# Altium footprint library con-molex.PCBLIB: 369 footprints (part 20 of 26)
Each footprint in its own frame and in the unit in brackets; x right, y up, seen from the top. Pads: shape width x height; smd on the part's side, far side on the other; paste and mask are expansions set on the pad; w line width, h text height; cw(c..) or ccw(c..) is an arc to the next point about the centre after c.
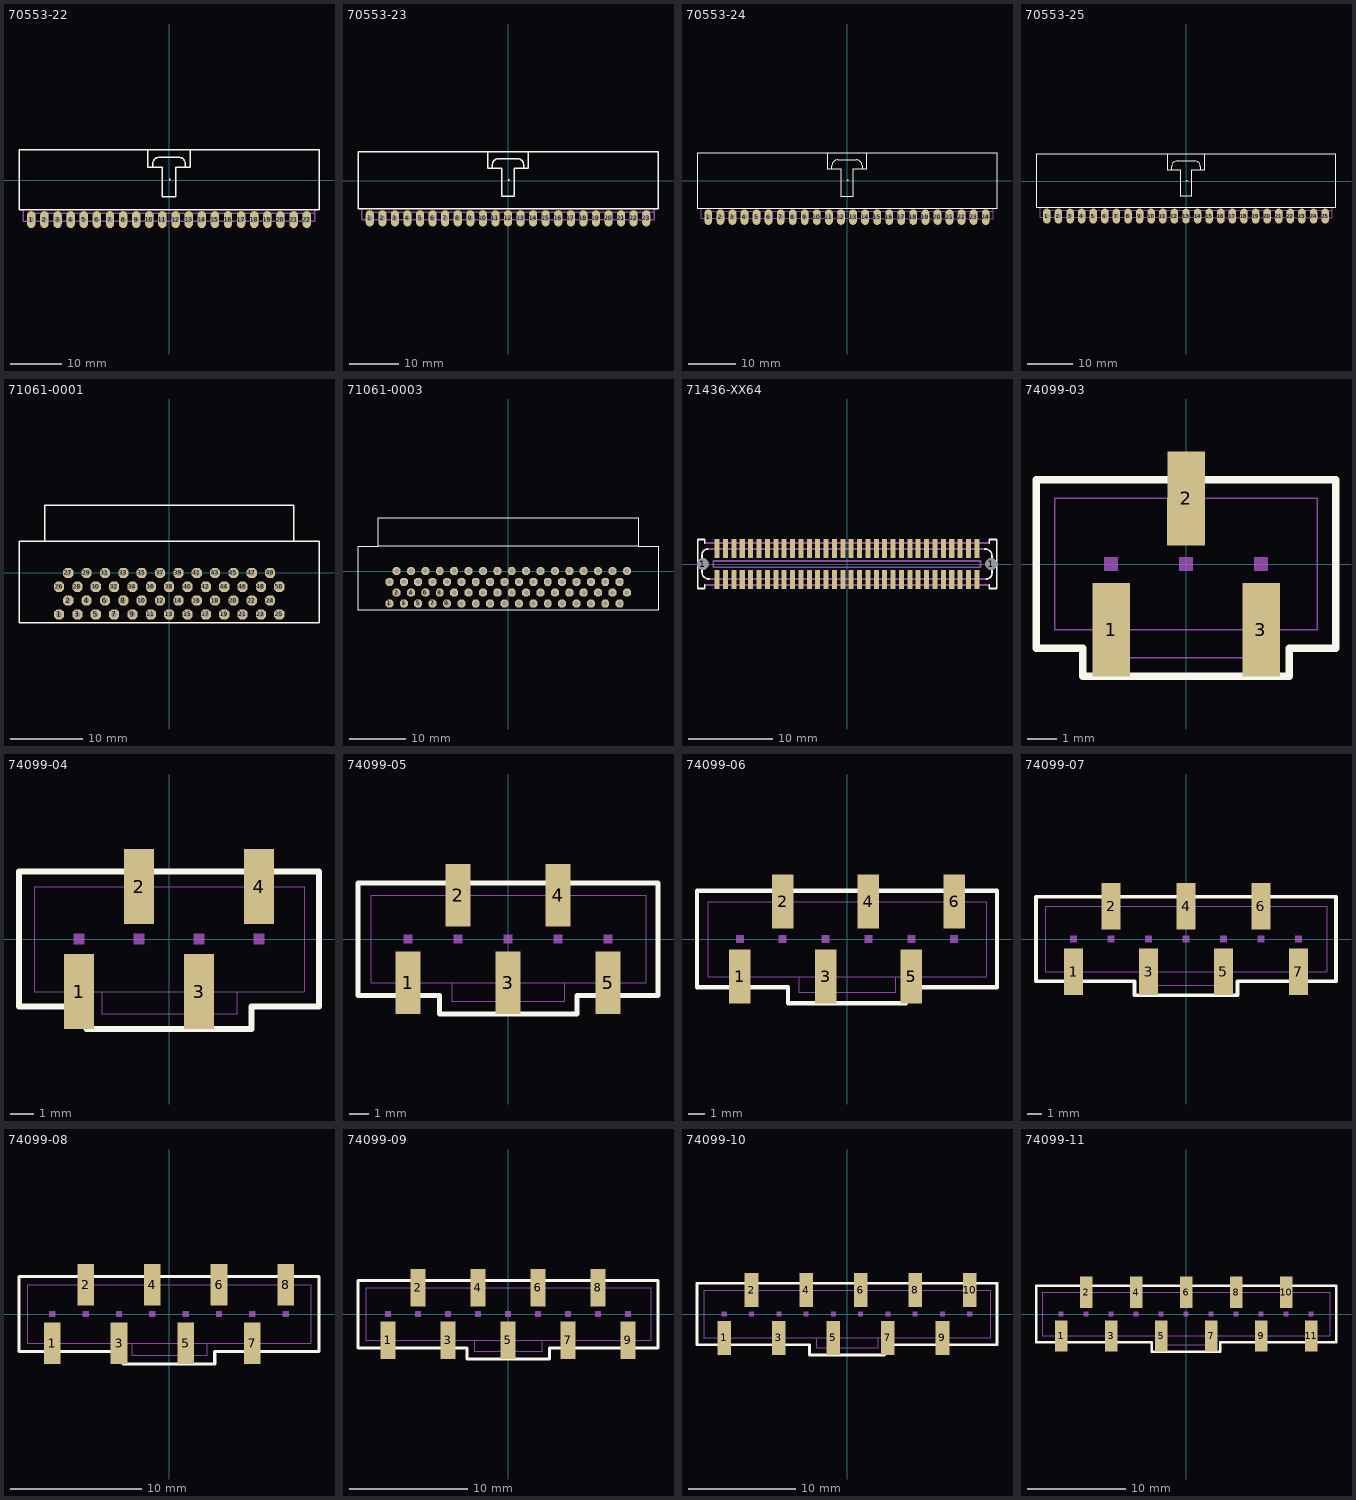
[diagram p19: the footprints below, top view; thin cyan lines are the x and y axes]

## 70553-22 [mil]
pads (22):
  oval 64.5x129 hole 43: 1(-1050,-300) 2(-950,-300) 3(-850,-300) 4(-750,-300) 5(-650,-300) 6(-550,-300) 7(-450,-300) 8(-350,-300) 9(-250,-300) 10(-150,-300) 11(-50,-300) 12(50,-300) 13(150,-300) 14(250,-300) 15(350,-300) 16(450,-300) 17(550,-300) 18(650,-300) 19(750,-300) 20(850,-300) 21(950,-300) 22(1050,-300)
Top Overlay:
  region: 0,0 10,0 10,10 0,10
  lines w10: -162.5,231.25 -162.5,100 -125,100 ; -125,100 -50,100 -50,-125 50,-125 50,100 125,100 ; -125,100 -125,125 cw(c-75,125) -75,175 75,175 cw(c75,125) 125,125 125,100 ; 125,100 162.5,100 162.5,231.25 ; 162.5,231.25 1143.75,231.25 1143.75,-225 -1143.75,-225 -1143.75,231.25 162.5,231.25
Mechanical 16:
  drawing of 178 lines, arcs and shapes, not listed

## 70553-23 [mil]
pads (23):
  oval 64.5x129 hole 43: 1(-1100,-300) 2(-1000,-300) 3(-900,-300) 4(-800,-300) 5(-700,-300) 6(-600,-300) 7(-500,-300) 8(-400,-300) 9(-300,-300) 10(-200,-300) 11(-100,-300) 12(0,-300) 13(100,-300) 14(200,-300) 15(300,-300) 16(400,-300) 17(500,-300) 18(600,-300) 19(700,-300) 20(800,-300) 21(900,-300) 22(1000,-300) 23(1100,-300)
Top Overlay:
  region: 0,0 10,0 10,10 0,10
  lines w10: -162.5,231.25 -162.5,100 -125,100 ; -125,100 -50,100 -50,-125 50,-125 50,100 125,100 ; -125,100 -125,125 cw(c-75,125) -75,175 75,175 cw(c75,125) 125,125 125,100 ; 125,100 162.5,100 162.5,231.25 ; 162.5,231.25 1193.75,231.25 1193.75,-225 -1193.75,-225 -1193.75,231.25 162.5,231.25
Mechanical 16:
  drawing of 186 lines, arcs and shapes, not listed

## 70553-24 [mil]
pads (24):
  oval 64.5x129 hole 43: 1(-1150,-300) 2(-1050,-300) 3(-950,-300) 4(-850,-300) 5(-750,-300) 6(-650,-300) 7(-550,-300) 8(-450,-300) 9(-350,-300) 10(-250,-300) 11(-150,-300) 12(-50,-300) 13(50,-300) 14(150,-300) 15(250,-300) 16(350,-300) 17(450,-300) 18(550,-300) 19(650,-300) 20(750,-300) 21(850,-300) 22(950,-300) 23(1050,-300) 24(1150,-300)
Top Overlay:
  region: 0,0 10,0 10,10 0,10
  lines w10: -162.5,231.25 -162.5,100 -125,100 ; -125,100 -50,100 -50,-125 50,-125 50,100 125,100 ; -125,100 -125,125 cw(c-75,125) -75,175 75,175 cw(c75,125) 125,125 125,100 ; 125,100 162.5,100 162.5,231.25 ; 162.5,231.25 1243.75,231.25 1243.75,-225 -1243.75,-225 -1243.75,231.25 162.5,231.25
Mechanical 16:
  drawing of 194 lines, arcs and shapes, not listed

## 70553-25 [mil]
pads (25):
  oval 64.5x129 hole 43: 1(-1200,-300) 2(-1100,-300) 3(-1000,-300) 4(-900,-300) 5(-800,-300) 6(-700,-300) 7(-600,-300) 8(-500,-300) 9(-400,-300) 10(-300,-300) 11(-200,-300) 12(-100,-300) 13(0,-300) 14(100,-300) 15(200,-300) 16(300,-300) 17(400,-300) 18(500,-300) 19(600,-300) 20(700,-300) 21(800,-300) 22(900,-300) 23(1000,-300) 24(1100,-300) 25(1200,-300)
Top Overlay:
  region: 0,0 10,0 10,10 0,10
  lines w10: -162.5,231.25 -162.5,100 -125,100 ; -125,100 -50,100 -50,-125 50,-125 50,100 125,100 ; -125,100 -125,125 cw(c-75,125) -75,175 75,175 cw(c75,125) 125,125 125,100 ; 125,100 162.5,100 162.5,231.25 ; 162.5,231.25 1293.75,231.25 1293.75,-225 -1293.75,-225 -1293.75,231.25 162.5,231.25
Mechanical 16:
  drawing of 202 lines, arcs and shapes, not listed

## 71061-0001 [mil]
pads (50):
  oct 55x55 hole 32: 1(-600,-225.59) 2(-550,-150.39) 3(-500,-225.59) 4(-450,-150.39) 5(-400,-225.59) 6(-350,-150.39) 7(-300,-225.59) 8(-250,-150.39) 9(-200,-225.59) 10(-150,-150.39) 11(-100,-225.59) 12(-50,-150.39) 13(0,-225.59) 14(50,-150.39) 15(100,-225.59) 16(150,-150.39) 17(200,-225.59) 18(250,-150.39) 19(300,-225.59) 20(350,-150.39) 21(400,-225.59) 22(450,-150.39) 23(500,-225.59) 24(550,-150.39) 25(600,-225.59) 26(-600,-75.2) 27(-550,0) 28(-500,-75.2) 29(-450,0) 30(-400,-75.2) 31(-350,0) 32(-300,-75.2) 33(-250,0) 34(-200,-75.2) 35(-150,0) 36(-100,-75.2) 37(-50,0) 38(0,-75.2) 39(50,0) 40(100,-75.2) 41(150,0) 42(200,-75.2) 43(250,0) 44(300,-75.2) 45(350,0) 46(400,-75.2) 47(450,0) 48(500,-75.2) 49(550,0) 50(600,-75.2)
Top Overlay:
  lines w8: -678.54,171.85 -818.31,171.85 -818.31,-271.06 816.34,-271.06 816.34,171.85 678.54,171.85 ; -678.54,171.85 -678.54,368.7 678.54,368.7 678.54,171.85 ; -678.54,171.85 678.54,171.85

## 71061-0003 [mil]
pads (68):
  oct 55x55 hole 32: 1(-825,-225.59) 2(-775,-150.39) 3(-725,-225.59) 4(-675,-150.39) 5(-625,-225.59) 6(-575,-150.39) 7(-525,-225.59) 8(-475,-150.39) 9(-425,-225.59) 10(-375,-150.39) 11(-325,-225.59) 12(-275,-150.39) 13(-225,-225.59) 14(-175,-150.39) 15(-125,-225.59) 16(-75,-150.39) 17(-25,-225.59) 18(25,-150.39) 19(75,-225.59) 20(125,-150.39) 21(175,-225.59) 22(225,-150.39) 23(275,-225.59) 24(325,-150.39) 25(375,-225.59) 26(425,-150.39) 27(475,-225.59) 28(525,-150.39) 29(575,-225.59) 30(625,-150.39) 31(675,-225.59) 32(725,-150.39) 33(775,-225.59) 34(825,-150.39) 35(-825,-75.2) 36(-775,0) 37(-725,-75.2) 38(-675,0) 39(-625,-75.2) 40(-575,0) 41(-525,-75.2) 42(-475,0) 43(-425,-75.2) 44(-375,0) 45(-325,-75.2) 46(-275,0) 47(-225,-75.2) 48(-175,0) 49(-125,-75.2) 50(-75,0) 51(-25,-75.2) 52(25,0) 53(75,-75.2) 54(125,0) 55(175,-75.2) 56(225,0) 57(275,-75.2) 58(325,0) 59(375,-75.2) 60(425,0) 61(475,-75.2) 62(525,0) 63(575,-75.2) 64(625,0) 65(675,-75.2) 66(725,0) 67(775,-75.2) 68(825,0)
Top Overlay:
  lines w8: -903.54,171.85 -1043.31,171.85 -1043.31,-271.06 1041.34,-271.06 1041.34,171.85 903.54,171.85 ; -903.54,171.85 -903.54,368.7 903.54,368.7 903.54,171.85 ; -903.54,171.85 903.54,171.85

## 71436-XX64 [mil]
pads (66):
  round 55.12 hole 55.12: 1(-677.17,0) 1(677.17,0)
  rect 23.62x90.55 smd: 1(-610.24,-72.83) 2(-570.87,-72.83) 3(-531.5,-72.83) 4(-492.13,-72.83) 5(-452.76,-72.83) 6(-413.39,-72.83) 7(-374.02,-72.83) 8(-334.65,-72.83) 9(-295.28,-72.83) 10(-255.91,-72.83) 11(-216.54,-72.83) 12(-177.17,-72.83) 13(-137.8,-72.83) 14(-98.43,-72.83) 15(-59.06,-72.83) 16(-19.69,-72.83) 17(19.69,-72.83) 18(59.06,-72.83) 19(98.43,-72.83) 20(137.8,-72.83) 21(177.17,-72.83) 22(216.54,-72.83) 23(255.91,-72.83) 24(295.28,-72.83) 25(334.65,-72.83) 26(374.02,-72.83) 27(413.39,-72.83) 28(452.76,-72.83) 29(492.13,-72.83) 30(531.5,-72.83) 31(570.87,-72.83) 32(610.24,-72.83) 33(-610.24,72.83) 34(-570.87,72.83) 35(-531.5,72.83) 36(-492.13,72.83) 37(-452.76,72.83) 38(-413.39,72.83) 39(-374.02,72.83) 40(-334.65,72.83) 41(-295.28,72.83) 42(-255.91,72.83) 43(-216.54,72.83) 44(-177.17,72.83) 45(-137.8,72.83) 46(-98.43,72.83) 47(-59.06,72.83) 48(-19.69,72.83) 49(19.69,72.83) 50(59.06,72.83) 51(98.43,72.83) 52(137.8,72.83) 53(177.17,72.83) 54(216.54,72.83) 55(255.91,72.83) 56(295.28,72.83) 57(334.65,72.83) 58(374.02,72.83) 59(413.39,72.83) 60(452.76,72.83) 61(492.13,72.83) 62(531.5,72.83) 63(570.87,72.83) 64(610.24,72.83)
Top Overlay:
  lines w8: -681.1,-39.37 ccw(c-649.21,-38.98) -648.82,-70.87 ; -681.1,-38.58 -681.1,40.16 cw(c-652.36,42.13) -654.33,70.87 ; -668.5,98.43 -668.5,114.96 -701.57,114.96 -701.57,-114.96 -667.72,-114.96 -667.72,-98.43 ; 648.82,70.87 cw(c649.21,38.98) 681.1,39.37 ; 654.33,-70.87 ccw(c652.36,-42.13) 681.1,-40.16 681.1,38.58 ; 667.72,98.43 667.72,114.96 703.15,114.96 703.15,-114.96 668.5,-114.96 668.5,-98.43
Mechanical 16:
  lines w8: -668.5,98.43 667.72,98.43 ; -667.72,-98.43 668.5,-98.43 ; -654.33,70.87 648.82,70.87 ; -648.82,-70.87 653.54,-70.87 654.33,-70.87 ; -628.35,-15.75 627.56,-15.75 627.56,14.17 -628.35,14.17 -628.35,-15.75

## 74099-03 [mil]
pads (3):
  rect 50x125 smd: 1(-100,-87.5) 2(0,87.5) 3(100,-87.5)
Top Overlay:
  lines w10: -200,-112.5 -200,112.5 200,112.5 200,-112.5 137.5,-112.5 137.5,-150 -137.5,-150 -137.5,-112.5 -200,-112.5
Mechanical 16:
  rectangle: -109.37,-9.37 -90.63,9.37
  rectangle: 90.63,-9.37 109.37,9.37
  rectangle: -9.37,-9.37 9.37,9.37
  lines w2: -112.5,-87.5 -175,-87.5 -175,87.5 175,87.5 175,-87.5 112.5,-87.5 ; -112.5,-87.5 112.5,-87.5 ; -112.5,-87.5 -112.5,-125 112.5,-125 112.5,-87.5
  text "1" at -162.5,-75 h62

## 74099-04 [mil]
pads (4):
  rect 50x125 smd: 1(-150,-87.5) 2(-50,87.5) 3(50,-87.5) 4(150,87.5)
Top Overlay:
  lines w10: -250,-112.5 -250,112.5 250,112.5 250,-112.5 137.5,-112.5 137.5,-150 -137.5,-150 -137.5,-112.5 -250,-112.5
Mechanical 16:
  rectangle: -59.37,-9.37 -40.63,9.37
  rectangle: -159.37,-9.37 -140.63,9.37
  rectangle: 140.63,-9.37 159.37,9.37
  rectangle: 40.63,-9.37 59.37,9.37
  lines w2: -112.5,-87.5 -225,-87.5 -225,87.5 225,87.5 225,-87.5 112.5,-87.5 ; -112.5,-87.5 112.5,-87.5 ; -112.5,-87.5 -112.5,-125 112.5,-125 112.5,-87.5
  text "1" at -212.5,-75 h62

## 74099-05 [mil]
pads (5):
  rect 50x125 smd: 1(-200,-87.5) 2(-100,87.5) 3(0,-87.5) 4(100,87.5) 5(200,-87.5)
Top Overlay:
  lines w10: -300,-112.5 -300,112.5 300,112.5 300,-112.5 137.5,-112.5 137.5,-150 -137.5,-150 -137.5,-112.5 -300,-112.5
Mechanical 16:
  rectangle: -9.37,-9.37 9.37,9.37
  rectangle: -109.37,-9.37 -90.63,9.37
  rectangle: 190.63,-9.37 209.37,9.37
  rectangle: 90.63,-9.37 109.37,9.37
  rectangle: -209.37,-9.37 -190.63,9.37
  lines w2: -112.5,-87.5 -275,-87.5 -275,87.5 275,87.5 275,-87.5 112.5,-87.5 ; -112.5,-87.5 112.5,-87.5 ; -112.5,-87.5 -112.5,-125 112.5,-125 112.5,-87.5
  text "1" at -262.5,-75 h62

## 74099-06 [mil]
pads (6):
  rect 50x125 smd: 1(-250,-87.5) 2(-150,87.5) 3(-50,-87.5) 4(50,87.5) 5(150,-87.5) 6(250,87.5)
Top Overlay:
  lines w10: -350,-112.5 -350,112.5 350,112.5 350,-112.5 137.5,-112.5 137.5,-150 -137.5,-150 -137.5,-112.5 -350,-112.5
Mechanical 16:
  rectangle: -59.37,-9.37 -40.63,9.37
  rectangle: -159.37,-9.37 -140.63,9.37
  rectangle: 140.63,-9.37 159.37,9.37
  rectangle: 40.63,-9.37 59.37,9.37
  rectangle: -259.37,-9.37 -240.63,9.37
  rectangle: 240.63,-9.37 259.37,9.37
  lines w2: -112.5,-87.5 -325,-87.5 -325,87.5 325,87.5 325,-87.5 112.5,-87.5 ; -112.5,-87.5 112.5,-87.5 ; -112.5,-87.5 -112.5,-125 112.5,-125 112.5,-87.5
  text "1" at -312.5,-75 h62

## 74099-07 [mil]
pads (7):
  rect 50x125 smd: 1(-300,-87.5) 2(-200,87.5) 3(-100,-87.5) 4(0,87.5) 5(100,-87.5) 6(200,87.5) 7(300,-87.5)
Top Overlay:
  lines w10: -400,-112.5 -400,112.5 400,112.5 400,-112.5 137.5,-112.5 137.5,-150 -137.5,-150 -137.5,-112.5 -400,-112.5
Mechanical 16:
  rectangle: -109.37,-9.37 -90.63,9.37
  rectangle: -209.37,-9.37 -190.63,9.37
  rectangle: 90.63,-9.37 109.37,9.37
  rectangle: -9.37,-9.37 9.37,9.37
  rectangle: -309.37,-9.37 -290.63,9.37
  rectangle: 190.63,-9.37 209.37,9.37
  rectangle: 290.63,-9.37 309.37,9.37
  lines w2: -112.5,-87.5 -375,-87.5 -375,87.5 375,87.5 375,-87.5 112.5,-87.5 ; -112.5,-87.5 112.5,-87.5 ; -112.5,-87.5 -112.5,-125 112.5,-125 112.5,-87.5
  text "1" at -362.5,-75 h62

## 74099-08 [mil]
pads (8):
  rect 50x125 smd: 1(-350,-87.5) 2(-250,87.5) 3(-150,-87.5) 4(-50,87.5) 5(50,-87.5) 6(150,87.5) 7(250,-87.5) 8(350,87.5)
Top Overlay:
  lines w10: -450,-112.5 -450,112.5 450,112.5 450,-112.5 137.5,-112.5 137.5,-150 -137.5,-150 -137.5,-112.5 -450,-112.5
Mechanical 16:
  rectangle: -159.37,-9.37 -140.63,9.37
  rectangle: -259.37,-9.37 -240.63,9.37
  rectangle: 40.63,-9.37 59.37,9.37
  rectangle: -59.37,-9.37 -40.63,9.37
  rectangle: -359.37,-9.37 -340.63,9.37
  rectangle: 140.63,-9.37 159.37,9.37
  rectangle: 240.63,-9.37 259.37,9.37
  rectangle: 340.63,-9.37 359.37,9.37
  lines w2: -112.5,-87.5 -425,-87.5 -425,87.5 425,87.5 425,-87.5 112.5,-87.5 ; -112.5,-87.5 112.5,-87.5 ; -112.5,-87.5 -112.5,-125 112.5,-125 112.5,-87.5
  text "1" at -412.5,-75 h62

## 74099-09 [mil]
pads (9):
  rect 50x125 smd: 1(-400,-87.5) 2(-300,87.5) 3(-200,-87.5) 4(-100,87.5) 5(0,-87.5) 6(100,87.5) 7(200,-87.5) 8(300,87.5) 9(400,-87.5)
Top Overlay:
  lines w10: -500,-112.5 -500,112.5 500,112.5 500,-112.5 137.5,-112.5 137.5,-150 -137.5,-150 -137.5,-112.5 -500,-112.5
Mechanical 16:
  rectangle: -209.37,-9.37 -190.63,9.37
  rectangle: -309.37,-9.37 -290.63,9.37
  rectangle: -9.37,-9.37 9.37,9.37
  rectangle: -109.37,-9.37 -90.63,9.37
  rectangle: -409.37,-9.37 -390.63,9.37
  rectangle: 90.63,-9.37 109.37,9.37
  rectangle: 190.63,-9.37 209.37,9.37
  rectangle: 290.63,-9.37 309.37,9.37
  rectangle: 390.63,-9.37 409.37,9.37
  lines w2: -112.5,-87.5 -475,-87.5 -475,87.5 475,87.5 475,-87.5 112.5,-87.5 ; -112.5,-87.5 112.5,-87.5 ; -112.5,-87.5 -112.5,-125 112.5,-125 112.5,-87.5
  text "1" at -462.5,-75 h62

## 74099-10 [mil]
pads (10):
  rect 50x125 smd: 1(-450,-87.5) 2(-350,87.5) 3(-250,-87.5) 4(-150,87.5) 5(-50,-87.5) 6(50,87.5) 7(150,-87.5) 8(250,87.5) 9(350,-87.5) 10(450,87.5)
Top Overlay:
  lines w10: -550,-112.5 -550,112.5 550,112.5 550,-112.5 137.5,-112.5 137.5,-150 -137.5,-150 -137.5,-112.5 -550,-112.5
Mechanical 16:
  rectangle: -259.37,-9.37 -240.63,9.37
  rectangle: -359.37,-9.37 -340.63,9.37
  rectangle: -59.37,-9.37 -40.63,9.37
  rectangle: -159.37,-9.37 -140.63,9.37
  rectangle: -459.37,-9.37 -440.63,9.37
  rectangle: 40.63,-9.37 59.37,9.37
  rectangle: 140.63,-9.37 159.37,9.37
  rectangle: 240.63,-9.37 259.37,9.37
  rectangle: 340.63,-9.37 359.37,9.37
  rectangle: 440.63,-9.37 459.37,9.37
  lines w2: -112.5,-87.5 -525,-87.5 -525,87.5 525,87.5 525,-87.5 112.5,-87.5 ; -112.5,-87.5 112.5,-87.5 ; -112.5,-87.5 -112.5,-125 112.5,-125 112.5,-87.5
  text "1" at -512.5,-75 h62

## 74099-11 [mil]
pads (11):
  rect 50x125 smd: 1(-500,-87.5) 2(-400,87.5) 3(-300,-87.5) 4(-200,87.5) 5(-100,-87.5) 6(0,87.5) 7(100,-87.5) 8(200,87.5) 9(300,-87.5) 10(400,87.5) 11(500,-87.5)
Top Overlay:
  lines w10: -600,-112.5 -600,112.5 600,112.5 600,-112.5 137.5,-112.5 137.5,-150 -137.5,-150 -137.5,-112.5 -600,-112.5
Mechanical 16:
  rectangle: -309.37,-9.37 -290.63,9.37
  rectangle: -409.37,-9.37 -390.63,9.37
  rectangle: -109.37,-9.37 -90.63,9.37
  rectangle: -209.37,-9.37 -190.63,9.37
  rectangle: -509.37,-9.37 -490.63,9.37
  rectangle: -9.37,-9.37 9.37,9.37
  rectangle: 90.63,-9.37 109.37,9.37
  rectangle: 190.63,-9.37 209.37,9.37
  rectangle: 290.63,-9.37 309.37,9.37
  rectangle: 390.63,-9.37 409.37,9.37
  rectangle: 490.63,-9.37 509.37,9.37
  lines w2: -112.5,-87.5 -575,-87.5 -575,87.5 575,87.5 575,-87.5 112.5,-87.5 ; -112.5,-87.5 112.5,-87.5 ; -112.5,-87.5 -112.5,-125 112.5,-125 112.5,-87.5
  text "1" at -562.5,-75 h62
